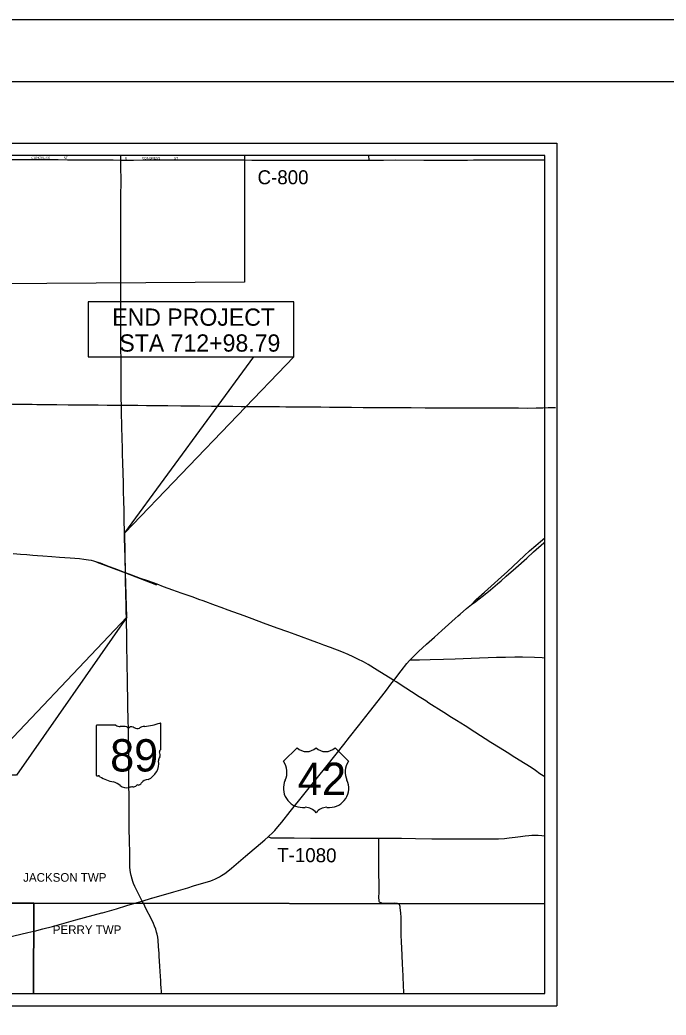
# Model space of a CAD drawing. Extents: x 0 to 72, y -85 to 22.
# Drawn here: x 4.64 to 9.89, y 13.93 to 22 of the extents above; entities that cross this region are included whole.
import ezdxf

# ---------------------------------------------------------------- set-up
doc = ezdxf.new("R2010")
doc.units = 0
for name, color, linetype in [('Default', 7, 'Continuous'), ('GM_X_Adjacent_County', 7, 'Continuous'), ('GM_X_Airport_Location_Class_2', 7, 'Continuous'), ('GM_X_County', 7, 'Continuous'), ('GM_X_County_Road', 7, 'Continuous'), ('GM_X_County_Road_Text', 7, 'Continuous'), ('GM_X_Interstate_Location', 7, 'Continuous'), ('GM_X_Minor_Lake', 7, 'Continuous'), ('GM_X_Minor_River_Text', 7, 'Continuous'), ('GM_X_Section', 7, 'Continuous'), ('GM_X_Section_Text', 7, 'Continuous'), ('GM_X_State_Location', 7, 'Continuous'), ('GM_X_Township', 7, 'Continuous'), ('GM_X_Township_Road', 7, 'Continuous'), ('GM_X_Township_Subdivision_Text', 7, 'Continuous'), ('GM_X_Township_Text', 7, 'Continuous'), ('GM_X_US_Location', 7, 'Continuous')]:
    doc.layers.add(name, color=color, linetype=linetype)

msp = doc.modelspace()

# ---------------------------------------------------------------- linework, layer by layer
at = {"layer": 'Default'}
for p, q in [((8.9, 20.9), (2.1, 20.9)), ((8.9, 20.9), (2.1, 20.9)), ((8.9, 14.1), (8.9, 20.9)), ((8.9, 14.1), (8.9, 20.9)), ((2.1, 14.1), (8.9, 14.1)), ((2.1, 14.1), (8.9, 14.1))]:
    msp.add_line(p, q, dxfattribs=at)
at = {"layer": 'GM_X_Adjacent_County'}
for points in [[(6.8636, 19.2649), (6.8636, 19.7119), (5.1955, 19.7119), (5.1955, 19.2649)], [(6.5404, 19.2649), (6.8636, 19.2649), (5.4913, 17.838)], [(4.6126, 15.8721), (4.2903, 15.8721), (5.5075, 17.154)]]:
    msp.add_lwpolyline(points, close=True, dxfattribs=at)
at = {"layer": 'GM_X_Airport_Location_Class_2'}
for p, q in [((6.8906, 16.0942), (6.7808, 15.9844)), ((7.3081, 15.9844), (7.1983, 16.0942)), ((6.9346, 15.6108), (6.9566, 15.6108)), ((7.1323, 15.6108), (7.1543, 15.6108))]:
    msp.add_line(p, q, dxfattribs=at)
for centre, radius, start, end in [((6.9676, 16.1727), 0.1099, 225.573, 314.427), ((7.1214, 16.1727), 0.1099, 225.573, 314.427), ((6.6548, 15.8961), 0.1538, 334.54712, 35.00093), ((7.4341, 15.8961), 0.1538, 144.99907, 205.45288), ((6.9329, 15.7646), 0.1538, 154.83192, 270.63826), ((7.156, 15.7646), 0.1538, 269.36174, 25.16808), ((6.9566, 15.501), 0.1099, 36.8699, 90), ((7.1323, 15.501), 0.1099, 90, 143.1301)]:
    msp.add_arc(centre, radius, start, end, dxfattribs=at)
at = {"layer": 'GM_X_County'}
msp.add_lwpolyline([(1.5, 21.5), (33.5, 21.5), (33.5, 0.5), (1.5, 0.5)], close=True, dxfattribs=at)
at = {"layer": 'GM_X_County_Road_Text'}
msp.add_line((7.4753, 20.8618), (7.4737, 20.9), dxfattribs=at)
for points in [[(4.459, 18.8836), (4.5056, 18.8836), (4.5801, 18.8824), (4.6484, 18.8819), (4.6918, 18.8815), (4.7414, 18.8808), (4.7787, 18.8804), (4.8595, 18.8799), (4.9092, 18.8798), (4.9403, 18.8794), (5.0333, 18.878), (5.0954, 18.8773), (5.2072, 18.8763), (5.2756, 18.8759), (5.3502, 18.8751), (5.4124, 18.8744), (5.4559, 18.8746), (5.4647, 18.8744)], [(5.4647, 18.8744), (5.5056, 18.8735), (5.5988, 18.8727), (5.6672, 18.8719), (5.7542, 18.8709), (5.8413, 18.8704), (5.947, 18.8694), (6.0278, 18.8686), (6.1024, 18.8679), (6.1956, 18.867), (6.2329, 18.8665), (6.3136, 18.8656), (6.3693, 18.8652), (6.4376, 18.8642), (6.4936, 18.864), (6.7482, 18.862), (6.7979, 18.8618), (6.8787, 18.8612), (7.0154, 18.8607), (7.0838, 18.8597), (7.1522, 18.8587), (7.2143, 18.8575), (7.2578, 18.8569), (7.3324, 18.8566), (7.4256, 18.8561), (7.7301, 18.8546), (7.7611, 18.8547), (7.8171, 18.8541), (7.929, 18.8533), (8.016, 18.8534), (8.0782, 18.8536), (8.2336, 18.8534), (8.3517, 18.8527), (8.4077, 18.8531), (8.4387, 18.8533), (8.5133, 18.8525), (8.6873, 18.8515), (8.7619, 18.8507), (8.8303, 18.8519), (8.8551, 18.8526), (8.8861, 18.8536), (8.9294, 18.8545), (8.9542, 18.8544), (8.9728, 18.8543), (8.9874, 18.8543)], [(6.6554, 15.3711), (6.6729, 15.3653), (6.6776, 15.3639), (6.683, 15.363), (6.7289, 15.3629), (6.8657, 15.3623), (6.999, 15.3615), (7.1689, 15.3607), (7.2802, 15.3615), (7.4049, 15.3607), (7.5254, 15.3615), (7.5541, 15.3613)], [(7.5649, 14.8379), (7.5606, 14.842), (7.5575, 14.8481), (7.5563, 14.852), (7.5554, 14.8581), (7.5549, 14.8766), (7.5559, 14.9262), (7.5557, 14.9606), (7.5556, 14.9972), (7.5555, 15.0181), (7.5548, 15.0475), (7.5539, 15.0807), (7.5544, 15.1427), (7.5545, 15.2542), (7.5542, 15.31), (7.5542, 15.3331), (7.5541, 15.3514), (7.5541, 15.3613)], [(7.5541, 15.3613), (7.7388, 15.3598), (7.8526, 15.3581), (7.9849, 15.3564), (8.0744, 15.3564), (8.1631, 15.3564), (8.2568, 15.3564), (8.4251, 15.3555), (8.4836, 15.3547), (8.5252, 15.3555), (8.5747, 15.3587), (8.6118, 15.3624), (8.6609, 15.3688), (8.7039, 15.3752), (8.741, 15.3802), (8.772, 15.3831), (8.7969, 15.3847), (8.8218, 15.3852), (8.8466, 15.3845), (8.8777, 15.3822), (8.9, 15.3799)], [(7.716, 14.8238), (7.7105, 14.827), (7.7046, 14.8293), (7.6985, 14.8306), (7.6922, 14.8314), (7.6796, 14.832), (7.6606, 14.8317), (7.6226, 14.8295), (7.6036, 14.8297), (7.591, 14.8309), (7.5785, 14.8331), (7.5724, 14.8347), (7.5649, 14.8379)], [(7.758, 14.1), (7.7571, 14.1189), (7.7553, 14.1561), (7.7516, 14.243), (7.747, 14.3423), (7.7408, 14.4726), (7.7391, 14.5142), (7.7365, 14.5781), (7.7364, 14.634), (7.7359, 14.6899), (7.7348, 14.721), (7.7329, 14.752), (7.7307, 14.7767), (7.7283, 14.7952), (7.7258, 14.8073), (7.7238, 14.8132), (7.7208, 14.8188), (7.716, 14.8238)]]:
    msp.add_lwpolyline(points, dxfattribs=at)
at = {"layer": 'GM_X_Interstate_Location'}
for points in [[(5.4602, 20.851), (5.4598, 20.863), (5.4592, 20.9)], [(5.4609, 20.1528), (5.4609, 20.1847), (5.4602, 20.4626), (5.4604, 20.5249), (5.461, 20.5972), (5.4616, 20.6612), (5.4616, 20.7146), (5.461, 20.7929), (5.461, 20.8235), (5.4602, 20.851)], [(5.4605, 19.8647), (5.4603, 19.9206), (5.4609, 20.0327), (5.4609, 20.1528)], [(5.461, 19.6746), (5.4611, 19.7022), (5.4605, 19.8203), (5.4605, 19.8647)], [(5.5317, 15.2328), (5.5305, 15.3463), (5.5285, 15.4312), (5.5272, 15.6075), (5.5266, 15.668), (5.5266, 15.7187), (5.5259, 15.774), (5.5253, 15.8549), (5.5246, 15.9174), (5.524, 15.9937), (5.5227, 16.1687), (5.522, 16.2338), (5.5201, 16.3318), (5.5174, 16.4219), (5.5155, 16.5166), (5.5148, 16.5785), (5.5148, 16.6344), (5.5135, 16.6864), (5.5122, 16.7298), (5.5109, 16.8094), (5.5083, 16.8969), (5.5076, 17.0002), (5.5057, 17.1206), (5.5037, 17.2252), (5.5004, 17.3673), (5.4991, 17.4317), (5.4978, 17.4982), (5.4974, 17.513), (5.4945, 17.6271), (5.4926, 17.7271), (5.4906, 17.783), (5.49, 17.8389), (5.4874, 17.9488), (5.486, 18.0291), (5.4847, 18.0876), (5.4821, 18.185), (5.4815, 18.2429), (5.4782, 18.3218), (5.4762, 18.4073), (5.4743, 18.4777), (5.4723, 18.5336), (5.4703, 18.5987), (5.4657, 18.8152), (5.4647, 18.8744), (5.4638, 18.9257), (5.4638, 19.0007), (5.4638, 19.0915), (5.4631, 19.2152), (5.4605, 19.3605), (5.4608, 19.6215), (5.461, 19.6746)], [(7.6749, 16.6402), (7.646, 16.6577), (7.5623, 16.7113), (7.5412, 16.7246), (7.4663, 16.7689), (7.4282, 16.7902), (7.3841, 16.8131), (7.3449, 16.8322), (7.3051, 16.85), (7.2534, 16.8714), (7.1606, 16.9072), (7.1081, 16.9263), (7.0793, 16.9378), (7.0502, 16.9488), (6.8749, 17.0125), (6.8165, 17.0338), (6.7288, 17.0654), (6.6178, 17.1058), (6.5247, 17.1407), (6.4604, 17.164), (6.332, 17.2109), (6.2739, 17.2326), (6.2271, 17.2494), (6.1279, 17.2856), (6.0927, 17.298), (6.0459, 17.3148), (5.9582, 17.3463), (5.9113, 17.3628), (5.882, 17.3731), (5.8064, 17.4012), (5.7539, 17.4206), (5.6778, 17.448), (5.6192, 17.4687), (5.5493, 17.4945), (5.4974, 17.513), (5.4908, 17.5154), (5.4268, 17.5393), (5.3459, 17.5712), (5.2937, 17.5912), (5.2642, 17.6013), (5.2402, 17.6082), (5.222, 17.6123), (5.1974, 17.6168), (5.1605, 17.622), (5.1234, 17.6261), (5.0491, 17.6318), (4.9625, 17.6385), (4.9005, 17.6436), (4.8262, 17.6492), (4.7828, 17.6525), (4.7456, 17.6552), (4.6962, 17.6589), (4.6467, 17.6627), (4.5847, 17.6673)], [(7.8082, 16.8076), (7.8245, 16.8078), (7.8827, 16.8088), (7.9709, 16.8107), (8.0792, 16.8138), (8.1724, 16.8168), (8.3028, 16.8213), (8.5078, 16.8282), (8.5824, 16.8302), (8.6569, 16.8316), (8.719, 16.8315), (8.8183, 16.8288), (8.8804, 16.8264), (8.9, 16.8252)], [(8.9, 15.8592), (8.862, 15.8837), (8.8265, 15.9086), (8.7904, 15.9331), (8.7429, 15.9627), (8.658, 16.0145), (8.5953, 16.0547), (8.5378, 16.0918), (8.4642, 16.1381), (8.3326, 16.2208), (8.254, 16.2709), (8.1857, 16.3141), (8.1439, 16.3408), (8.0808, 16.3806), (7.9603, 16.4573), (7.9344, 16.4745), (7.8819, 16.5077), (7.8192, 16.5481), (7.7722, 16.5784), (7.6938, 16.6288), (7.6749, 16.6402)], [(5.6331, 14.8507), (5.587, 14.9411), (5.5734, 14.9691), (5.5636, 14.9921), (5.5572, 15.0096), (5.5516, 15.0275), (5.5438, 15.0577), (5.5388, 15.0821), (5.5361, 15.1007), (5.5339, 15.1255), (5.5331, 15.1661), (5.5318, 15.2299), (5.5317, 15.2328)], [(5.7706, 14.4252), (5.7668, 14.4827), (5.7627, 14.5321), (5.7593, 14.5567), (5.7546, 14.5809), (5.7502, 14.599), (5.7428, 14.6226), (5.7342, 14.6458), (5.7244, 14.6685), (5.7056, 14.7077), (5.6668, 14.7855), (5.6428, 14.8325), (5.6414, 14.8353), (5.6385, 14.8407), (5.6331, 14.8507)], [(5.7901, 14.1), (5.789, 14.1169), (5.787, 14.1478), (5.7854, 14.1726), (5.7834, 14.2036), (5.7812, 14.2408), (5.7792, 14.278), (5.7767, 14.3214), (5.7721, 14.4021), (5.7706, 14.4252)]]:
    msp.add_lwpolyline(points, dxfattribs=at)
at = {"layer": 'GM_X_Minor_Lake'}
for points in [[(8.9, 14.8286), (4.755, 14.8337), (4.5196, 14.8337), (4.428, 20.9)], [(2.1, 14.8468), (3.516, 14.8392), (4.5196, 14.8337), (4.755, 14.8337), (4.7514, 14.1)], [(4.7514, 14.1), (4.755, 14.8337), (8.9, 14.8286)]]:
    msp.add_lwpolyline(points, dxfattribs=at)
at = {"layer": 'GM_X_Minor_River_Text'}
for points in [[(6.4631, 20.8634), (6.5241, 20.8632), (6.6111, 20.8629), (6.6545, 20.8629), (6.7352, 20.8629), (6.8159, 20.8628), (6.9276, 20.8628), (7.0828, 20.862), (7.1635, 20.862), (7.2876, 20.8619), (7.3682, 20.862), (7.4365, 20.8621), (7.4753, 20.8618)], [(7.4753, 20.8618), (7.4985, 20.8616), (7.5916, 20.863), (7.6908, 20.8641), (7.9203, 20.8631), (8.032, 20.8619), (8.1189, 20.8623), (8.1859, 20.8626), (8.2728, 20.8631), (8.3224, 20.8636), (8.3597, 20.8638), (8.4278, 20.8639), (8.4712, 20.8644), (8.5332, 20.8642), (8.6015, 20.8644), (8.6636, 20.8648), (8.7008, 20.8647), (8.8808, 20.8655), (8.9, 20.8657)]]:
    msp.add_lwpolyline(points, dxfattribs=at)
at = {"layer": 'GM_X_Section'}
msp.add_lwpolyline([(0, 0), (34, 0), (34, 22), (0, 22)], close=True, dxfattribs=at)
at = {"layer": 'GM_X_Section_Text'}
for points in [[(4.4859, 20.8737), (4.4866, 20.8734), (4.4926, 20.8712), (4.4987, 20.8696), (4.5051, 20.8687), (4.5113, 20.8683), (4.5548, 20.8679), (4.6292, 20.8681), (4.6726, 20.8678), (4.7284, 20.8676), (4.7903, 20.8675), (4.8709, 20.8676), (4.9515, 20.8666), (5.0258, 20.8658), (5.1498, 20.865), (5.218, 20.865), (5.2924, 20.8644), (5.3978, 20.8644), (5.4598, 20.863)], [(5.4598, 20.863), (5.4828, 20.8629), (5.5202, 20.863), (5.5637, 20.8632), (5.6446, 20.8637), (5.7816, 20.8647), (5.8563, 20.8646), (5.9186, 20.8648), (5.9995, 20.8653), (6.0867, 20.8655), (6.1552, 20.8653), (6.2921, 20.8649), (6.4631, 20.8634)]]:
    msp.add_lwpolyline(points, dxfattribs=at)
at = {"layer": 'GM_X_State_Location'}
for points in [[(8.3054, 17.2569), (8.345, 17.2969), (8.4103, 17.3556), (8.4656, 17.4056), (8.5488, 17.4805), (8.5945, 17.5226), (8.7358, 17.6537), (8.7771, 17.6912), (8.8288, 17.7358), (8.8665, 17.7683), (8.9, 17.7975)], [(8.1978, 17.164), (8.2147, 17.1787), (8.2663, 17.2236), (8.3054, 17.2569), (8.3375, 17.2783), (8.3583, 17.2937), (8.4029, 17.3287), (8.461, 17.375), (8.5181, 17.423), (8.5459, 17.4477), (8.5873, 17.4853), (8.6664, 17.5554), (8.7547, 17.6339), (8.8103, 17.6836), (8.8937, 17.7582), (8.9, 17.7638)], [(5.7097, 14.8734), (5.7106, 14.8737), (5.8896, 14.9262), (6.003, 14.959), (6.0506, 14.9736), (6.1342, 14.9977), (6.1816, 15.0127), (6.2051, 15.0212), (6.2281, 15.0308), (6.245, 15.0389), (6.2615, 15.0479), (6.2775, 15.0577), (6.3032, 15.0753), (6.3283, 15.0937), (6.3573, 15.1172), (6.4708, 15.214), (6.6274, 15.3466), (6.6554, 15.3711), (6.6648, 15.3794), (6.6874, 15.4008), (6.709, 15.4233), (6.7337, 15.4514), (6.7654, 15.4897), (6.8356, 15.5769), (7.0445, 15.8397), (7.1334, 15.9516), (7.2693, 16.1215), (7.3153, 16.1803), (7.3888, 16.2727), (7.4772, 16.3851), (7.607, 16.5519), (7.6599, 16.621), (7.6749, 16.6402), (7.7361, 16.7192), (7.7823, 16.7777), (7.8024, 16.8013), (7.8082, 16.8076), (7.8233, 16.8242), (7.845, 16.8464), (7.8764, 16.8764), (7.9408, 16.9349), (8.0056, 16.9929), (8.066, 17.0467), (8.1726, 17.1419), (8.1978, 17.164)], [(5.6331, 14.8507), (5.7097, 14.8734)], [(5.3098, 14.7555), (5.425, 14.788), (5.5082, 14.8135), (5.5724, 14.8326), (5.6331, 14.8507)], [(4.5355, 14.5559), (4.7053, 14.5943), (4.7542, 14.6056), (4.7598, 14.6069), (4.826, 14.6241), (4.9039, 14.6451), (5.0955, 14.6979), (5.3054, 14.7543), (5.3098, 14.7555)]]:
    msp.add_lwpolyline(points, dxfattribs=at)
at = {"layer": 'GM_X_Township'}
for p, q in [((2, 21), (9, 21)), ((9, 21), (9, 14)), ((2, 14), (9, 14))]:
    msp.add_line(p, q, dxfattribs=at)
for points in [[(5.5075, 17.154), (5.4974, 17.513), (5.4913, 17.838)], [(5.5075, 17.154), (5.4974, 17.513), (5.4913, 17.838)], [(5.2642, 17.6013), (5.4974, 17.513), (5.7501, 17.416)], [(5.2642, 17.6013), (5.4974, 17.513), (5.7501, 17.416)]]:
    msp.add_lwpolyline(points, dxfattribs=at)
at = {"layer": 'GM_X_Township_Subdivision_Text'}
msp.add_lwpolyline([(6.4631, 20.9), (6.4627, 19.8722), (4.4549, 19.8575), (4.4327, 20.9)], dxfattribs=at)
at = {"layer": 'GM_X_US_Location'}
for p, q in [((5.2593, 16.2716), (5.2593, 15.8736)), ((5.418, 16.2784), (5.2645, 16.2784)), ((5.7837, 16.0801), (5.7837, 16.2883)), ((5.7837, 16.0801), (5.7837, 16.0801))]:
    msp.add_line(p, q, dxfattribs=at)
for centre, radius, start, end in [((5.2653, 16.2724), 0.00608, 98.1301, 188.1301), ((5.4546, 16.3246), 0.0589, 231.61951, 271.11188), ((5.4742, 16.055), 0.2115, 80.48669, 94.98827), ((5.5222, 16.2745), 0.017, 219.79206, 297.10237), ((5.5471, 16.2285), 0.0353, 54.46668, 119.14113), ((5.5928, 16.2916), 0.0425, 233.85621, 294.82819), ((5.6678, 16.1569), 0.1119, 97.34618, 120.76885), ((5.5969, 16.8211), 0.5561, 275.84447, 288.90645), ((5.7779, 16.2892), 0.00584, 351.86209, 97.738), ((5.7824, 16.0648), 0.00903, 107.94398, 210.33697), ((5.7775, 16.0793), 0.00625, 289.60381, 7.73413), ((5.8046, 15.993), 0.0395, 136.8065, 186.92959), ((5.7249, 16.0385), 0.0542, 340.03296, 23.64957), ((5.6281, 15.9665), 0.1391, 292.30889, 8.98584), ((5.2654, 15.8727), 0.00613, 171.95839, 258.30661), ((5.2663, 15.9134), 0.0468, 267.33899, 280.60386), ((5.2759, 15.8506), 0.0169, 29.74838, 93.27175), ((5.4888, 16.2082), 0.4016, 240.41292, 257.1985), ((5.6867, 15.7618), 0.0762, 94.40312, 142.57675), ((5.3691, 15.6948), 0.1257, 47.18416, 75.83597), ((5.505, 15.8486), 0.0797, 230.70037, 286.29184), ((5.551, 15.711), 0.0655, 85.69512, 111.20995), ((5.5569, 15.8188), 0.0425, 268.77702, 315.54927), ((5.5953, 15.7803), 0.012, 65.75173, 132.64842), ((5.5902, 15.835), 0.0449, 282.87319, 323.27711)]:
    msp.add_arc(centre, radius, start, end, dxfattribs=at)

# ---------------------------------------------------------------- texts
at = {"layer": 'GM_X_Adjacent_County'}
for s, height, p in [('END PROJECT', 0.14, (5.3901, 19.5184)), ('STA 712+98.79', 0.14, (5.4481, 19.3084)), ('JACKSON TWP', 0.07, (4.6672, 15.0072)), ('PERRY TWP', 0.07, (4.9077, 14.583))]:
    msp.add_text(s, height=height, dxfattribs=at).set_placement(p)
at = {"layer": 'GM_X_Airport_Location_Class_2'}
msp.add_text('42', height=0.26367, dxfattribs=at).set_placement((6.896, 15.7097))
at = {"layer": 'GM_X_County_Road'}
msp.add_text('C-800', height=0.11364, rotation=0.00312, dxfattribs=at).set_placement((6.5695, 20.6663))
at = {"layer": 'GM_X_Township_Road'}
msp.add_text('T-1080', height=0.11364, rotation=359.53123, dxfattribs=at).set_placement((6.7284, 15.1681))
at = {"layer": 'GM_X_Township_Text'}
for s, height, p in [('CONGRESS', 0.01894, (4.734, 20.8723)), ('ST', 0.01894, (4.9957, 20.8706)), ('E', 0.0189, (5.494, 20.8689)), ('CONGRESS', 0.01894, (5.6307, 20.8689)), ('ST', 0.01894, (5.8907, 20.8689))]:
    msp.add_text(s, height=height, rotation=0.00001, dxfattribs=at).set_placement(p)
at = {"layer": 'GM_X_US_Location'}
msp.add_text('89', height=0.26221, dxfattribs=at).set_placement((5.3733, 15.9016))

doc.saveas('drawing.dxf')
